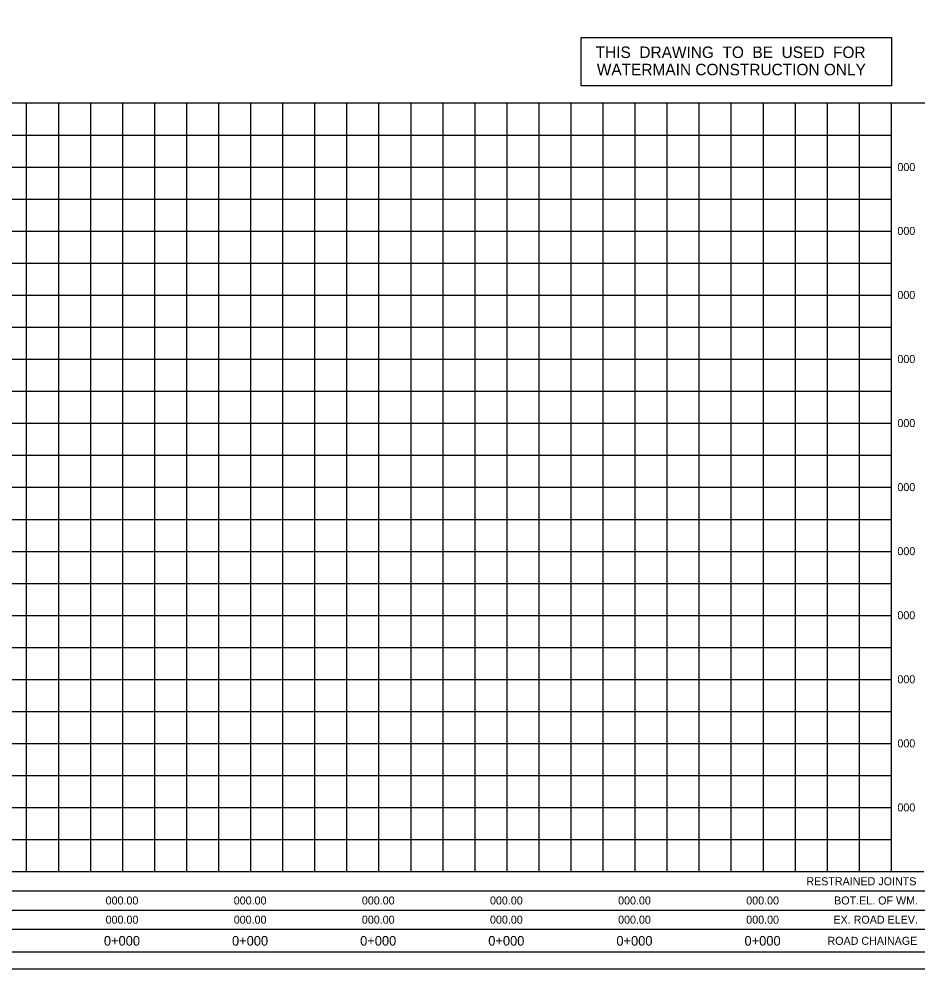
# Model space of a CAD drawing. Extents: x 613360 to 613780, y 4825621 to 4825911.
# Drawn here: x 613569.5 to 613709.9, y 4825620.9 to 4825769.2 of the extents above; entities that cross this region are included whole.
import ezdxf

# ---------------------------------------------------------------- set-up
doc = ezdxf.new("R2010")
doc.units = 0
for name, color, linetype in [('G-ANNO-TEXT', 7, 'Continuous'), ('G-GRID-MAJ', 7, 'Continuous'), ('G-GRID-MIN', 7, 'Continuous'), ('G-TTLB-OTLN', 7, 'Continuous'), ('G-TTLB-OTLN-PB', 7, 'Continuous')]:
    doc.layers.add(name, color=color, linetype=linetype)

msp = doc.modelspace()

# ---------------------------------------------------------------- linework, layer by layer
at = {"layer": 'G-ANNO-TEXT'}
msp.add_lwpolyline([(613657.3, 4825766.32), (613705.73, 4825766.31), (613705.73, 4825758.79), (613657.3, 4825758.8)], close=True, dxfattribs=at)
at = {"layer": 'G-GRID-MAJ'}
for p, q in [((613585.73, 4825636.11), (613585.73, 4825756.11)), ((613605.73, 4825636.11), (613605.73, 4825756.11)), ((613625.73, 4825636.11), (613625.73, 4825756.11)), ((613645.73, 4825636.11), (613645.73, 4825756.11)), ((613665.73, 4825636.11), (613665.73, 4825756.11)), ((613685.73, 4825636.11), (613685.73, 4825756.11)), ((613705.73, 4825636.11), (613705.73, 4825756.11)), ((613385.73, 4825746.11), (613705.73, 4825746.11)), ((613385.73, 4825736.11), (613705.73, 4825736.11)), ((613385.73, 4825726.11), (613705.73, 4825726.11)), ((613385.73, 4825716.11), (613705.73, 4825716.11)), ((613385.73, 4825706.11), (613705.73, 4825706.11)), ((613385.73, 4825696.11), (613705.73, 4825696.11)), ((613385.73, 4825686.11), (613705.73, 4825686.11)), ((613385.73, 4825676.11), (613705.73, 4825676.11)), ((613385.73, 4825666.11), (613705.73, 4825666.11)), ((613385.73, 4825656.11), (613705.73, 4825656.11)), ((613385.73, 4825646.11), (613705.73, 4825646.11))]:
    msp.add_line(p, q, dxfattribs=at)
at = {"layer": 'G-GRID-MIN'}
for p, q in [((613570.73, 4825636.11), (613570.73, 4825756.11)), ((613575.73, 4825636.11), (613575.73, 4825756.11)), ((613580.73, 4825636.11), (613580.73, 4825756.11)), ((613590.73, 4825636.11), (613590.73, 4825756.11)), ((613595.73, 4825636.11), (613595.73, 4825756.11)), ((613600.73, 4825636.11), (613600.73, 4825756.11)), ((613610.73, 4825636.11), (613610.73, 4825756.11)), ((613615.73, 4825636.11), (613615.73, 4825756.11)), ((613620.73, 4825636.11), (613620.73, 4825756.11)), ((613630.73, 4825636.11), (613630.73, 4825756.11)), ((613635.73, 4825636.11), (613635.73, 4825756.11)), ((613640.73, 4825636.11), (613640.73, 4825756.11)), ((613650.73, 4825636.11), (613650.73, 4825756.11)), ((613655.73, 4825636.11), (613655.73, 4825756.11)), ((613660.73, 4825636.11), (613660.73, 4825756.11)), ((613670.73, 4825636.11), (613670.73, 4825756.11)), ((613675.73, 4825636.11), (613675.73, 4825756.11)), ((613680.73, 4825636.11), (613680.73, 4825756.11)), ((613690.73, 4825636.11), (613690.73, 4825756.11)), ((613695.73, 4825636.11), (613695.73, 4825756.11)), ((613700.73, 4825636.11), (613700.73, 4825756.11)), ((613385.73, 4825751.11), (613705.73, 4825751.11)), ((613385.73, 4825741.11), (613705.73, 4825741.11)), ((613385.73, 4825731.11), (613705.73, 4825731.11)), ((613385.73, 4825721.11), (613705.73, 4825721.11)), ((613385.73, 4825711.11), (613705.73, 4825711.11)), ((613385.73, 4825701.11), (613705.73, 4825701.11)), ((613385.73, 4825691.11), (613705.73, 4825691.11)), ((613385.73, 4825681.11), (613705.73, 4825681.11)), ((613385.73, 4825671.11), (613705.73, 4825671.11)), ((613385.73, 4825661.11), (613705.73, 4825661.11)), ((613385.73, 4825651.11), (613705.73, 4825651.11)), ((613385.73, 4825641.11), (613705.73, 4825641.11))]:
    msp.add_line(p, q, dxfattribs=at)
at = {"layer": 'G-TTLB-OTLN'}
for p, q in [((613380.09, 4825756.11), (613774.18, 4825756.11)), ((613380.09, 4825636.11), (613710.78, 4825636.11)), ((613380.09, 4825633.11), (613774.18, 4825633.11)), ((613380.09, 4825630.11), (613749.42, 4825630.11)), ((613380.09, 4825627.11), (613749.42, 4825627.11))]:
    msp.add_line(p, q, dxfattribs=at)
msp.add_lwpolyline([(613380.09, 4825892.08), (613774.18, 4825892.08), (613774.18, 4825623.51), (613380.09, 4825623.51)], close=True, dxfattribs=at)
at = {"layer": 'G-TTLB-OTLN-PB'}
msp.add_lwpolyline([(613359.58, 4825620.91), (613780.27, 4825620.91), (613780.27, 4825894.68), (613359.58, 4825894.68)], close=True, dxfattribs=at)

# ---------------------------------------------------------------- texts
at = {"layer": 'G-ANNO-TEXT'}
for s, height, rotation, p in [('THIS  DRAWING  TO  BE  USED  FOR', 1.8, 359.9969, (613659.56, 4825763.13)), ('WATERMAIN CONSTRUCTION ONLY', 1.8, 359.9969, (613659.74, 4825760.43)), ('000', 1.25, 360, (613706.66, 4825735.51)), ('000', 1.25, 360, (613706.66, 4825725.51)), ('000', 1.25, 360, (613706.66, 4825715.51)), ('000', 1.25, 360, (613706.66, 4825705.51)), ('000', 1.25, 360, (613706.66, 4825695.51)), ('000', 1.25, 360, (613706.66, 4825685.51)), ('000', 1.25, 360, (613706.66, 4825675.51)), ('000', 1.25, 360, (613706.66, 4825665.51)), ('000', 1.25, 360, (613706.66, 4825655.51)), ('000', 1.25, 360, (613706.66, 4825645.51))]:
    msp.add_text(s, height=height, rotation=rotation, dxfattribs=at).set_placement(p)
for s, height, p in [('000', 1.25, (613706.66, 4825745.48)), ('RESTRAINED JOINTS', 1.25, (613692.44, 4825633.98)), ('000.00', 1.25, (613583.06, 4825630.98)), ('000.00', 1.25, (613603.06, 4825630.98)), ('000.00', 1.25, (613623.06, 4825630.98)), ('000.00', 1.25, (613643.06, 4825630.98)), ('000.00', 1.25, (613663.06, 4825630.98)), ('000.00', 1.25, (613683.06, 4825630.98)), ('BOT.EL. OF WM.', 1.25, (613696.78, 4825630.98)), ('000.00', 1.25, (613583.06, 4825627.98)), ('000.00', 1.25, (613603.06, 4825627.98)), ('000.00', 1.25, (613623.06, 4825627.98)), ('000.00', 1.25, (613643.06, 4825627.98)), ('000.00', 1.25, (613663.06, 4825627.98)), ('000.00', 1.25, (613683.06, 4825627.98)), ('EX. ROAD ELEV.', 1.25, (613696.67, 4825627.98)), ('0+000', 1.5, (613582.79, 4825624.56)), ('0+000', 1.5, (613602.79, 4825624.56)), ('0+000', 1.5, (613622.79, 4825624.56)), ('0+000', 1.5, (613642.79, 4825624.56)), ('0+000', 1.5, (613662.79, 4825624.56)), ('0+000', 1.5, (613682.79, 4825624.56)), ('ROAD CHAINAGE', 1.25, (613695.74, 4825624.68))]:
    msp.add_text(s, height=height, dxfattribs=at).set_placement(p)

doc.saveas('drawing.dxf')
